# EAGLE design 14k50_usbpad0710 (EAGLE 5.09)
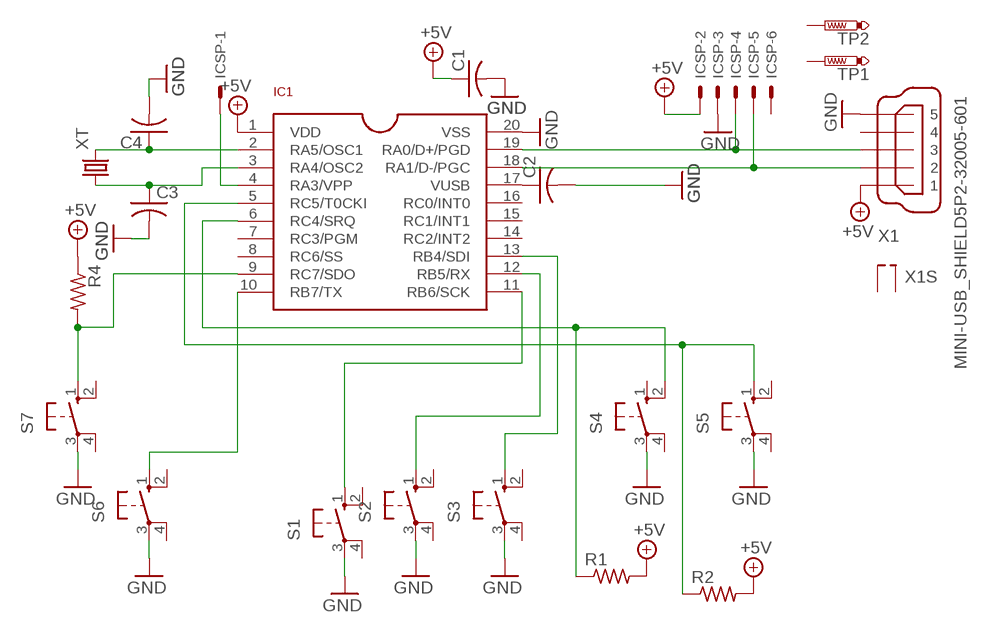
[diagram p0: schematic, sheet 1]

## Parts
C1  C-US025-024X044  [C025-024X044]
C2  C-US025-024X044  [C025-024X044]
C3  C-US025-024X044  [C025-024X044]
C4  C-US025-024X044  [C025-024X044]
IC1  18F14K50-I/P  [DIL20]
ICSP  22-23-2061  [22-23-2061]
R1  R-US_0204/5  [0204/5]
R2  R-US_0204/5  [0204/5]
R4  R-US_0204/5  [0204/5]
S1  10-XX  [B3F-10XX]
S2  10-XX  [B3F-10XX]
S3  10-XX  [B3F-10XX]
S4  10-XX  [B3F-10XX]
S5  10-XX  [B3F-10XX]
S6  10-XX  [B3F-10XX]
S7  10-XX  [B3F-10XX]
TP1  PTR1PAD1-13Y  [P1-13Y]
TP2  PTR1PAD1-13Y  [P1-13Y]
X1  MINI-USB_SHIELD5P2-32005-601  [32005-601]
XT  CRYSTALHC49S  [HC49/S]

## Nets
+5V [pow]: C1.1 IC1.1(VDD) ICSP.2 R1.2 R2.2 R4.1 X1.1
GND [pow]: C1.2 C2.2 C3.2 C4.2 IC1.20(VSS) ICSP.3 S1.3(P) S2.3(P) S3.3(P) S4.3(P) S5.3(P) S6.3(P) S7.3(P) X1.5
N$1: C2.1 IC1.17(VUSB)
N$2: IC1.4(RA3/VPP) ICSP.1
N$3: IC1.5(RC5/T0CKI) R2.1 S5.1(S)
N$5: IC1.11(RB6/SCK) S1.1(S)
N$6: IC1.6(RC4/SRQ) R1.1 S4.2(S1)
N$7: IC1.13(RB4/SDI) S3.1(S)
N$8: IC1.9(RC7/SDO) R4.2 S7.1(S)
N$9: IC1.10(RB7/TX) S6.1(S)
N$10: IC1.12(RB5/RX) S2.1(S)
N$32: C3.1 IC1.3(RA4/OSC2) XT.1
N$36: IC1.18(RA1/D-/PGC) ICSP.5 X1.2
N$44: IC1.19(RA0/D+/PGD) ICSP.4 X1.3
N$71: C4.1 IC1.2(RA5/OSC1) XT.2
Unconnected: IC1.7(RC3/PGM) IC1.8(RC6/SS) IC1.14(RC2/INT2) IC1.15(RC1/INT1) IC1.16(RC0/INT0) ICSP.6 S1.2(S1) S1.4(P1) S2.2(S1) S2.4(P1) S3.2(S1) S3.4(P1) S4.1(S) S4.4(P1) S5.2(S1) S5.4(P1) S6.2(S1) S6.4(P1) S7.2(S1) S7.4(P1) TP1.1(TP) TP2.1(TP) X1.4 X1.M1(S1) X1.M2(S2)

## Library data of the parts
C1-C4 = rcl:C-US: CAPACITOR, American symbol
IC1 = motorola_hc08:18F14K50-I/P
ICSP = con-molex:22-23-2061: .100" (2.54mm) Center Header - 6 Pin
R1 R2 R4 = rcl:R-US_: RESISTOR, American symbol
S1-S7 = switch-omron:10-XX: OMRON SWITCH
TP1 TP2 = testpad:PTR1: TEST PIN
X1 = con-cypressindustries:MINI-USB_SHIELD5P2-: MINI USB-B R/A DIP 5pol. Source: www.cypressindustries.com
XT = crystal:CRYSTAL: CRYSTAL

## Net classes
1 pow: width 0.635 mm

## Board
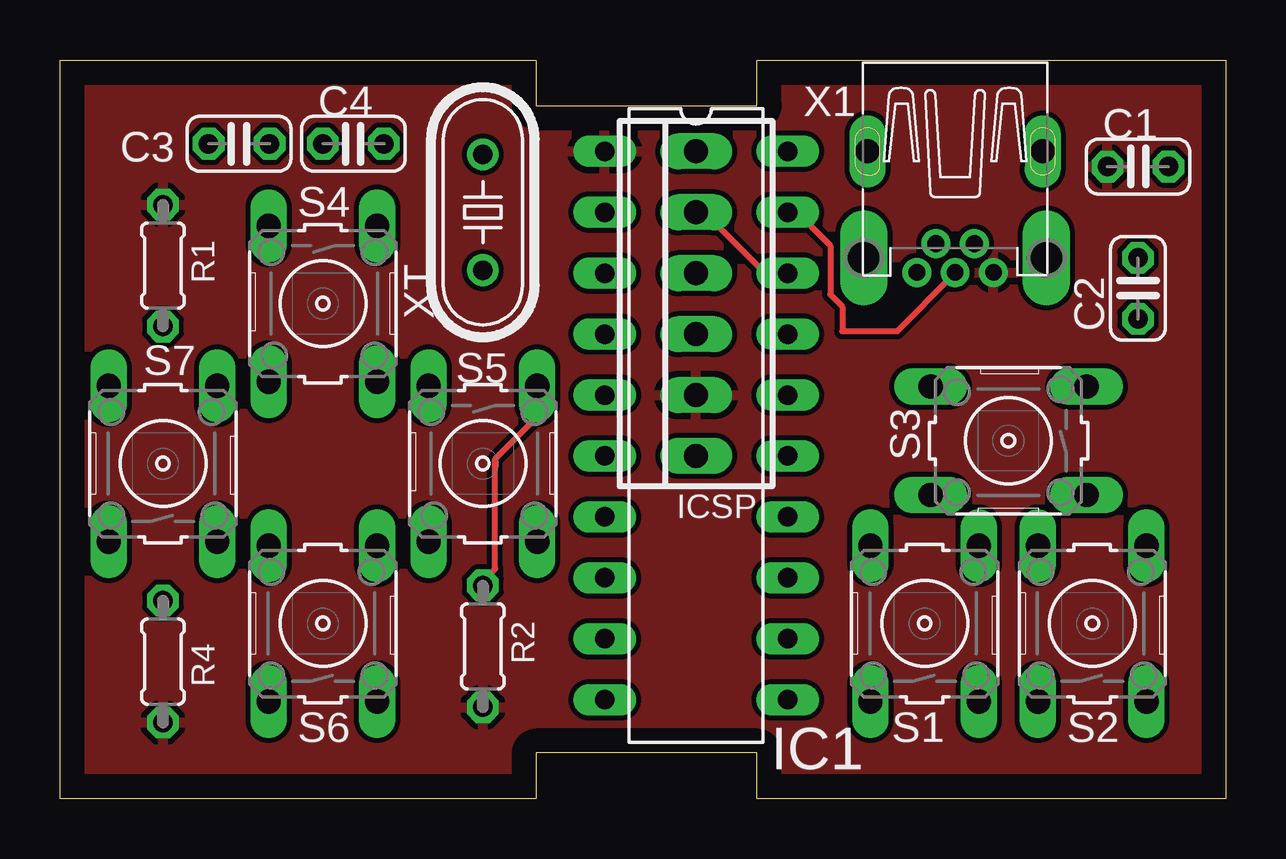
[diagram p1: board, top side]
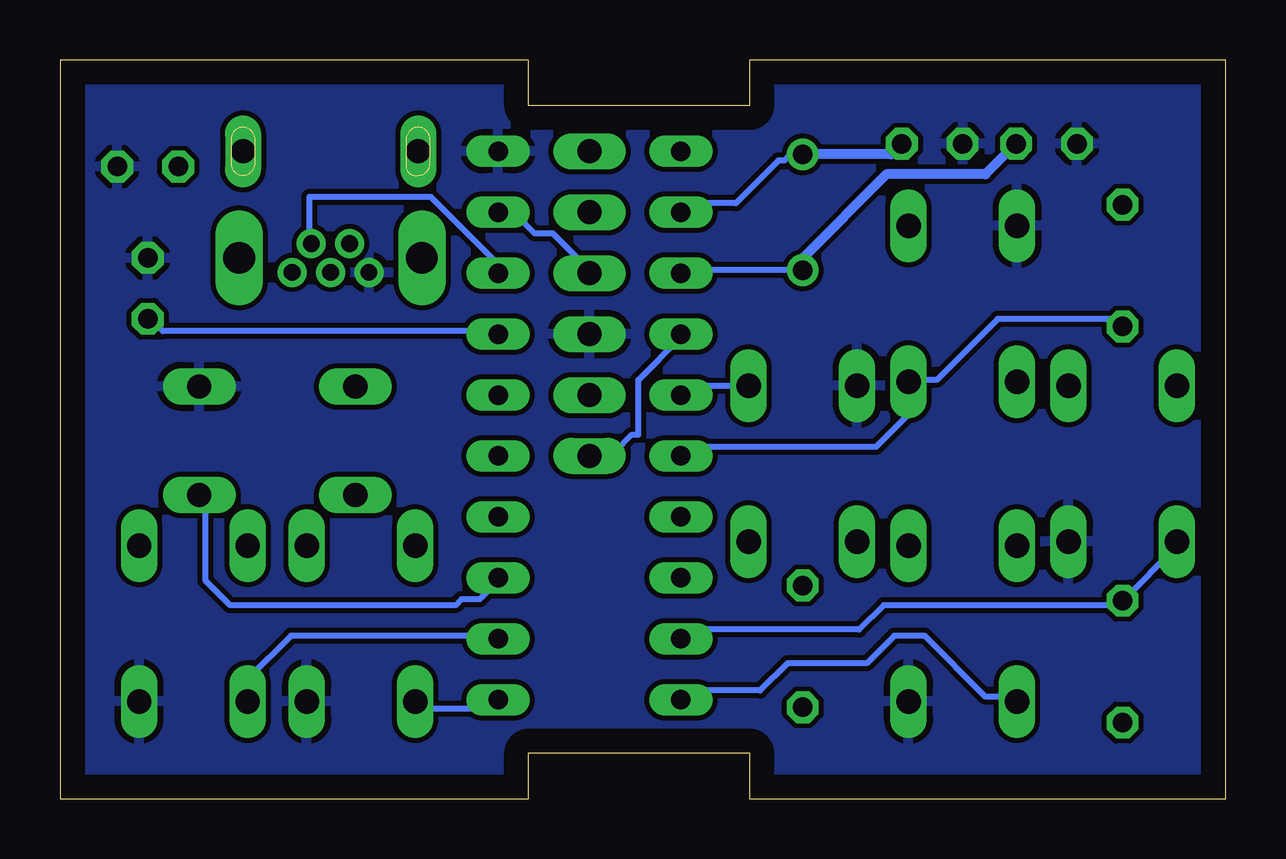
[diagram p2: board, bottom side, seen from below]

Size 48.59 x 30.8 mm. Coordinates in mm from the lower left corner, seen from the top.
Outline: 48.59,0 29.06,0 29.06,1.91 19.85,1.91 19.85,0 0,0 0,30.79 19.85,30.79 19.85,28.89 29.06,28.89 29.06,30.8 48.59,30.79 48.59,0
Copper layers (1*16): Top 0.0356mm / dielectric 1.5011mm / Bottom 0.0356mm
Design rules "SilverCircuits": minimum track width 10mil, minimum drill 24mil, track to track 8mil, track to pad 8mil, pad to pad 8mil, via to via 8mil, smd to smd 8mil, copper to edge 40mil, drill to drill 8mil, minimum pad ring 10mil, minimum via ring 8mil, stop-mask expansion 4mil, vias tented up to drill 0mil, thermal gap 10mil

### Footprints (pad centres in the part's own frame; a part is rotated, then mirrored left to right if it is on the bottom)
C025-024X044 = drill 0.813 octagon: 1 -1.27,0; 2 1.27,0
DIL20 = drill 0.813 long: 1 -11.43,-3.81; 2 -8.89,-3.81; 3 -6.35,-3.81; 4 -3.81,-3.81; 5 -1.27,-3.81; 6 1.27,-3.81; 7 3.81,-3.81; 8 6.35,-3.81; 9 8.89,-3.81; 10 11.43,-3.81; 11 11.43,3.81; 12 8.89,3.81; 13 6.35,3.81; 14 3.81,3.81; 15 1.27,3.81; 16 -1.27,3.81; 17 -3.81,3.81; 18 -6.35,3.81; 19 -8.89,3.81; 20 -11.43,3.81
22-23-2061 = drill 1 long: 1 -6.35,0; 2 -3.81,0; 3 -1.27,0; 4 1.27,0; 5 3.81,0; 6 6.35,0
0204/5 = drill 0.813 octagon: 1 -2.54,0; 2 2.54,0
B3F-10XX = drill 1.016 long: 1 -3.251,2.261; 2 3.251,2.261; 3 -3.251,-2.261; 4 3.251,-2.261
P1-13Y = drill 1.321 pad 1.905 long: 1 0,0
32005-601 = drill 0.7 pad 1.016 round: 1 2.825,1.6; 2 1.625,0.8; 3 2.825,0; 4 1.625,-0.8; 5 2.825,-1.6 | drill 1 pad 1.422 long: M1 -2.225,3.65; M2 -2.225,-3.65
HC49/S = drill 0.813 round: 1 -2.413,0; 2 2.413,0

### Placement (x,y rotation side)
C1  44.93,26.35 0 top
C2  44.93,21.27 90 top
C3  7.47,27.3 180 top
C4  12.23,27.3 180 top
IC1  26.52,15.56 270 top
ICSP  26.52,20.64 90 top
R1  4.29,22.23 90 top
R2  17.63,6.35 270 top
R4  4.29,5.71 90 top
S1  36.04,7.3 90 top
S2  43.03,7.3 90 top
S3  39.53,14.92 180 top
S4  10.96,20.64 270 top
S5  17.63,13.97 270 top
S6  10.96,7.3 90 top
S7  4.29,13.97 90 top
TP1  33.5,22.54 0 top
TP2  41.12,22.54 0 top
X1  37.31,24.77 270 top
XT  17.63,24.45 90 top

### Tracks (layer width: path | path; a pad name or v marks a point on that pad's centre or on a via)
+5V
  pour Top: -0.15,31.12 49.06,31.12 49.06,-0.32 -0.15,-0.32
GND
  pour Bottom: -0.15,31.12 49.69,31.12 49.38,-0.32 -0.47,-0.63
N$1
  Bottom 0.254: IC1.17 30.33,19.49 44.3,19.49 44.81,20 C2.1
N$2
  Bottom 0.254: IC1.4 22.71,19.24 24.49,17.46 24.49,15.18 24.74,15.18 25.5,14.41 26.52,14.41 ICSP.1
N$3
  Top 0.254: R2.1 17.63,9.08 18.14,9.59 18.14,14.16 19.66,15.68 19.66,17.21 S5.1
  Bottom 0.254: IC1.5 22.71,16.95 22.45,17.21 19.91,17.21 S5.1
N$5
  Bottom 0.254: IC1.11 30.33,4 30.58,3.75 33.38,3.75 33.63,4 S1.1
N$6
  Bottom 0.254: R1.1 4.42,19.75 4.67,20 9.5,20 12.04,17.46 13.06,17.46 S4.2 13.31,17.21 13.31,15.94 14.58,14.67 22.45,14.67 22.71,14.41 IC1.6
N$7
  Bottom 0.254: IC1.13 30.33,9.08 31.09,8.32 31.85,8.32 32.11,8.06 41.5,8.06 42.52,9.08 42.52,12.64 42.77,12.64 S3.1
N$8
  Bottom 0.254: IC1.9 22.71,6.79 22.45,7.05 15.28,7.05 14.26,8.06 4.42,8.06 R4.2 2.03,10.52 S7.1
N$9
  Bottom 0.254: IC1.10 22.71,4.25 22.45,4.51 19.41,4.51 18.26,5.65 14.96,5.65 13.82,6.79 12.55,6.79 10.01,4.25 8.74,4.25 S6.1
N$10
  Bottom 0.254: IC1.12 30.33,6.79 38.96,6.79 40.74,5.02 40.74,4.25 S2.1
N$32
  Bottom 0.254: XT.1 22.58,22.03 IC1.3
  Bottom 0.406: XT.1 17.63,22.54 14.13,26.03 10.01,26.03 C3.1
N$36
  Top 0.254: ICSP.5 26.84,24.45 29.37,21.91 IC1.18
  Bottom 0.254: X1.2 38.2,23.3 38.2,25.08 33.12,25.08 30.33,22.29 IC1.18
N$44
  Top 0.254: X1.3 37.19,21.78 34.9,19.49 32.61,19.49 32.61,20.51 32.11,21.02 32.11,23.05 30.84,24.32 30.33,24.32 IC1.19
  Bottom 0.254: ICSP.4 26.52,22.03 28.04,23.56 28.8,23.56 29.57,24.32 30.33,24.32 IC1.19
N$71
  Bottom 0.254: XT.2 18.14,26.86 18.39,26.61 18.64,26.61 20.42,24.83 22.45,24.83 22.71,24.57 IC1.2
  Bottom 0.406: XT.2 13.94,26.86 C4.1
